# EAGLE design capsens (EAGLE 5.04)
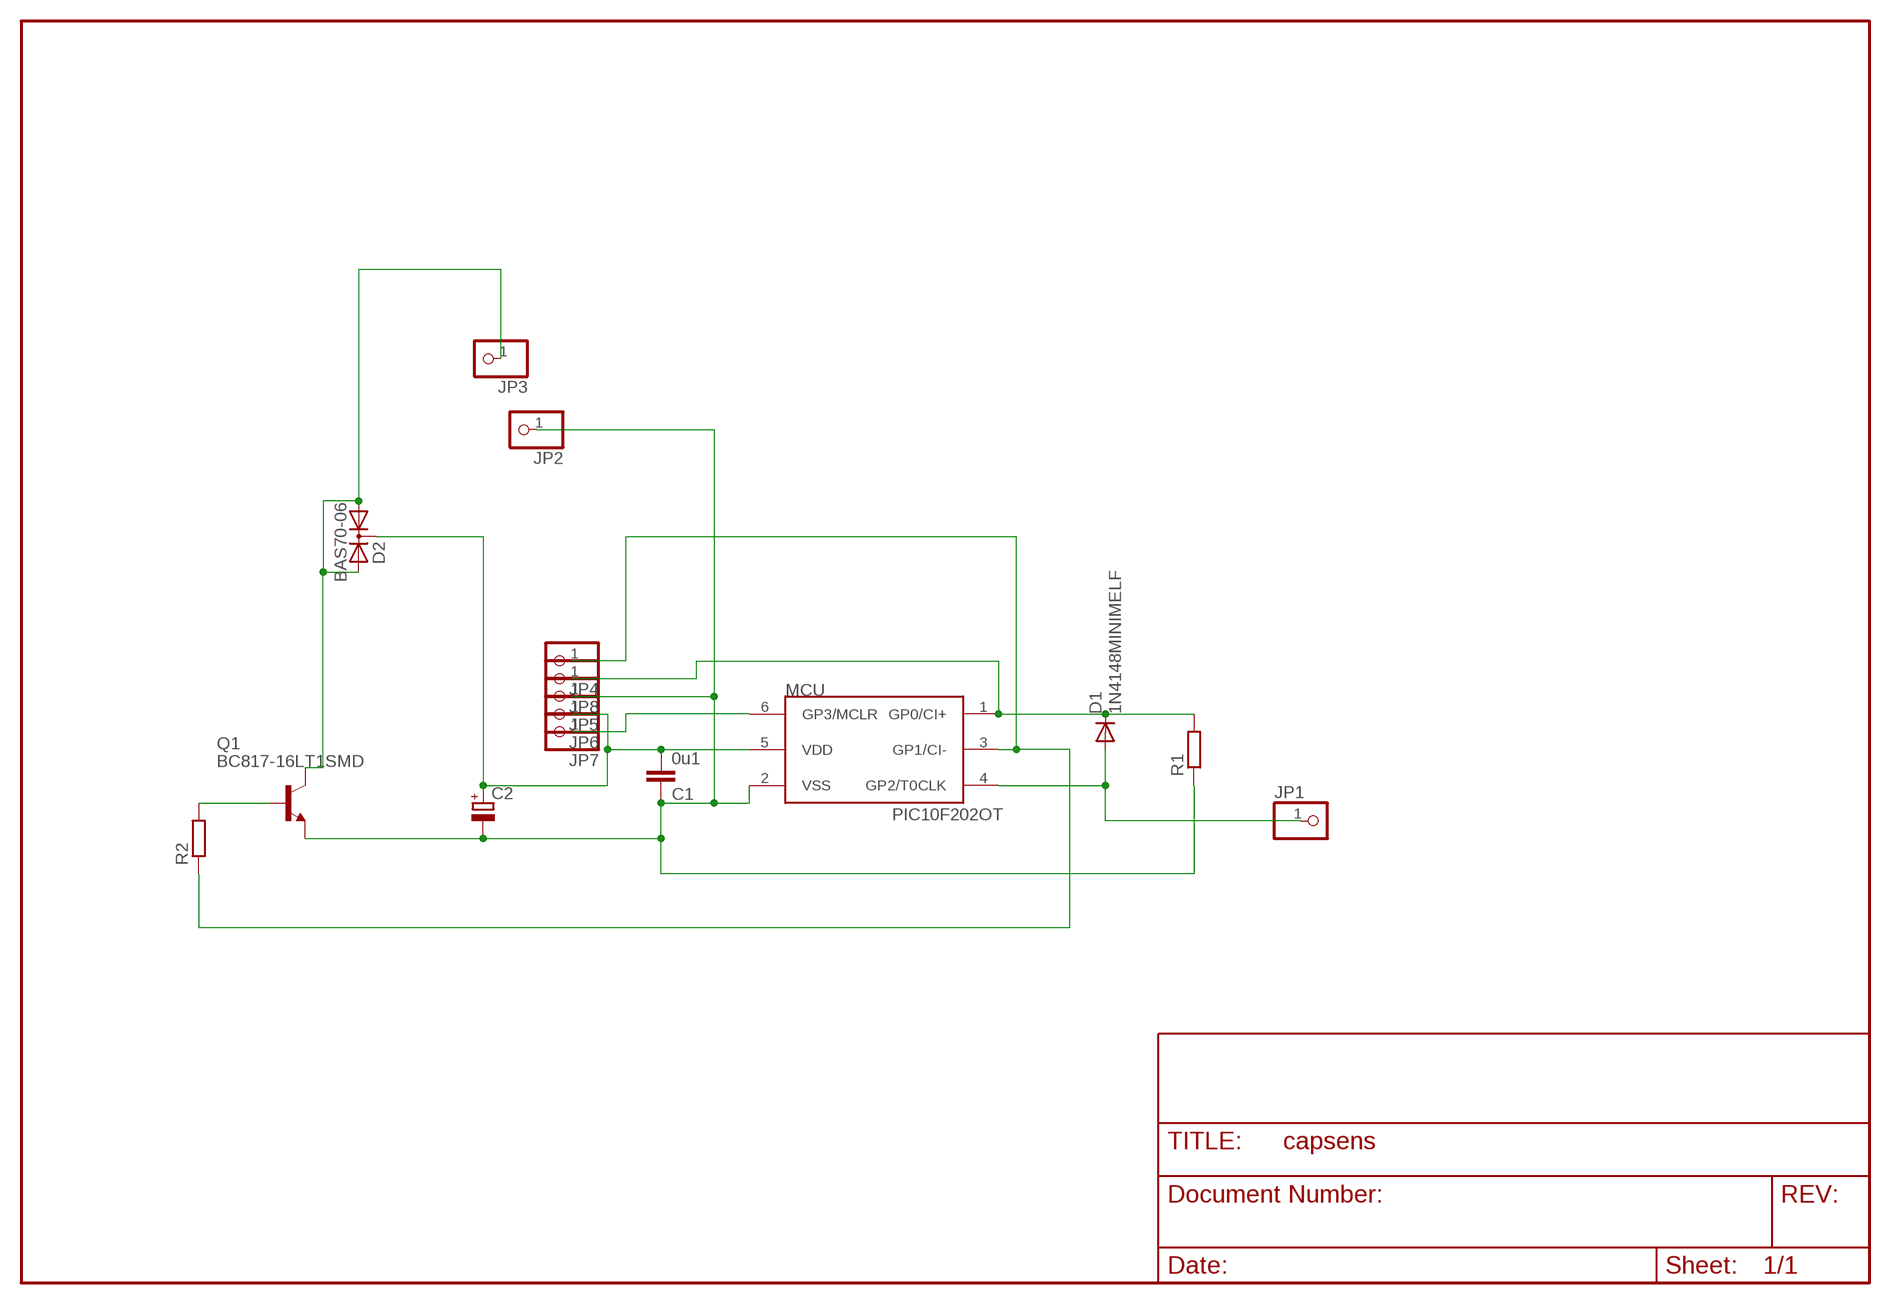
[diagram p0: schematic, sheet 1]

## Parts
C1  0u1  C-EUC1206  [C1206]
C2  CPOL-EUF  [PANASONIC_F]
D1  1N4148MINIMELF  [MINIMELF]
D2  BAS70-06  [SOT23]
JP1  PINHD-1X1  [1X01]
JP2  PINHD-1X1  [1X01]
JP3  PINHD-1X1  [1X01]
JP4  PINHD-1X1  [1X01]
JP5  PINHD-1X1  [1X01]
JP6  PINHD-1X1  [1X01]
JP7  PINHD-1X1  [1X01]
JP8  PINHD-1X1  [1X01]
MCU  PIC10F202OT  [SOT23-6]
Q1  BC817-16LT1SMD  [SOT23-BEC]
R1  R-EU_R1206  [R1206]
R2  R-EU_R1206  [R1206]

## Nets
GP0: D1.C JP8.1 MCU.1(GP0/CI+) R1.2
GP1: JP4.1 MCU.3(GP1/CI-) R2.1
GP2: D1.A JP1.1 MCU.4(GP2/T0CLK)
GP3: JP7.1 MCU.6(GP3/MCLR)
N$1: D2.1(A1) D2.2(A2) JP3.1 Q1.C
N$4: Q1.B R2.2
VDD1: C1.2 C2.+ D2.3(C) JP6.1 MCU.5(VDD)
VSS1: C1.1 C2.- JP2.1 JP5.1 MCU.2(VSS) Q1.E R1.1

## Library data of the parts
C1 = rcl:C-EU: CAPACITOR, European symbol
C2 = rcl-2:CPOL-EU: POLARIZED CAPACITOR, European symbol
D1 = diode-1:1N4148: DIODE
D2 = diode-1:BAS70-06: Silicon Schottky Diodes General-purpose diode for high-speed switching
JP1-JP8 = pinhead(2):PINHD-1X1: PIN HEADER
MCU = microchip-3:PIC10F2*: uPC nW 0,25/0,5k Program Flash memory Comparator
Q1 = transistor-npn:BC817*: NPN Transistor
R1 R2 = rcl-2:R-EU_: RESISTOR, European symbol

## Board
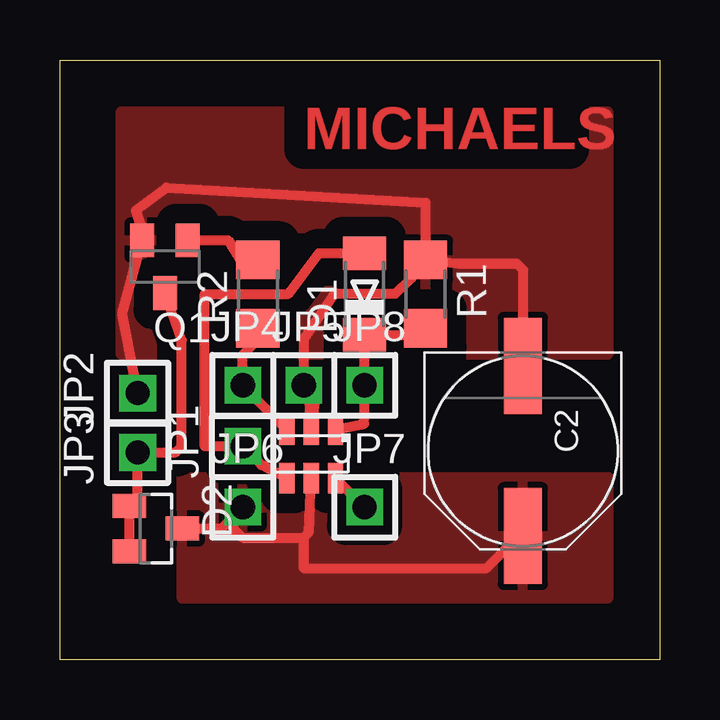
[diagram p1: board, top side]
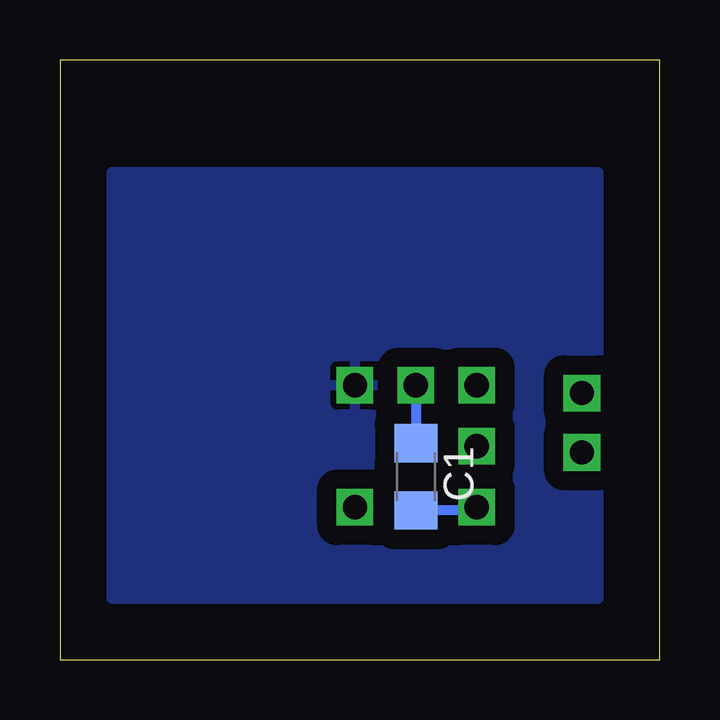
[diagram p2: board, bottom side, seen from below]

Size 25 x 25 mm. Coordinates in mm from the lower left corner, seen from the top.
Outline: 0,0 0,25 25,25 25,0 0,0
Copper layers (1*16): Top 0.035mm / dielectric 1.5mm / Bottom 0.035mm
Design rules "default": minimum track width 10mil, minimum drill 24mil, track to track 8mil, track to pad 8mil, pad to pad 8mil, via to via 8mil, smd to smd 8mil, copper to edge 40mil, drill to drill 8mil, minimum pad ring 10mil, minimum via ring 8mil, stop-mask expansion 4mil, vias tented up to drill 0mil, thermal gap 10mil

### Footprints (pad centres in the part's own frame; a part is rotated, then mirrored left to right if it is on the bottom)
C1206 = smd 1.6 x 1.8: 1 -1.4,0; 2 1.4,0
PANASONIC_F = smd 4 x 1.6: + 3.55,0; - -3.55,0
MINIMELF = smd 1.4 x 1.8: A 1.7,0; C -1.7,0
SOT23 = smd 1 x 1.4: 1 -0.95,-1.1; 2 0.95,-1.1; 3 0,1.1
1X01 = drill 1.016 square: 1 0,0
SOT23-6 = smd 0.635 x 1.27: 1 -1.016,-1.016; 2 0,-1.016; 3 1.016,-1.016; 4 1.016,1.016; 5 0,1.016; 6 -1.016,1.016
SOT23-BEC = smd 1 x 1.4: B -0.95,-1.1; C 0,1.1; E 0.95,-1.1
R1206 = smd 1.6 x 1.803: 1 -1.422,0; 2 1.422,0

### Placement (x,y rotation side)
C1  10.16,7.62 270 bottom
C2  19.3,8.7 270 top
D1  12.7,15.24 90 top
D2  4,5.46 270 top
JP1  7.62,8.89 90 top
JP2  3.24,11.11 90 top
JP3  3.24,8.64 90 top
JP4  7.62,11.43 0 top
JP5  10.16,11.43 0 top
JP6  7.62,6.35 0 top
JP7  12.7,6.35 0 top
JP8  12.7,11.43 0 top
MCU  10.48,8.57 180 top
Q1  4.38,16.38 180 top
R1  15.24,15.24 270 top
R2  8.26,15.24 90 top

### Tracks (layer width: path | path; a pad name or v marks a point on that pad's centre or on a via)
GP0
  Top 0.406: MCU.1 12.68,9.82 12.7,10.16 JP8.1 D1.C 14.33,13.54 R1.2
  pour Bottom (isolate 0.813): 2.54,20.32 22.86,20.32 22.86,2.54 2.54,2.54
GP1
  Top 0.406: MCU.3 9.37,9.68 JP4.1 7.62,12.7 8.74,13.82 R2.1
GP2
  Top 0.406: MCU.4 8.4,8.11 JP1.1 6.03,8.89 6.03,15.24 9.53,15.24 10.79,16.94 D1.A
GP3
  Top 0.406: MCU.6 JP7.1
N$1
  Top 0.406: Q1.C 5.08,13.31 5.08,8.89 4.83,8.64 JP3.1 3.24,6.75 D2.1 D2.2
N$4
  Top 0.406: Q1.B 7,17.48 7.62,16.51 8.74,16.51 R2.2
VDD1
  Top 0.406: D2.3 6.73,5.46 6.99,5.71 | 6.99,5.71 JP6.1 | MCU.5 10.38,5.3 10.16,5.08 | 10.16,5.08 7.62,5.08 6.99,5.71 | C2.+ 19.12,5.15 17.78,3.81 10.16,3.81 10.16,5.08
  Bottom 0.406: C1.2 7.75,6.22 JP6.1
  pour Top (isolate 0.813): 15.24,7.62 22.86,7.62 22.86,2.54 5.08,2.54 5.08,7.62 12.7,7.62
VSS1
  Top 0.406: JP2.1 2.6,14.43 Q1.E 3.49,17.74 3.17,18.73 4.45,19.68 15.24,19.05 R1.1 | C2.- 19.3,16.26 19.05,16.51 16.66,16.51 R1.1 | 10.38,11.21 MCU.2 10.7,11.34 JP5.1 10.16,13.34 11.43,15.24 13.97,15.24 14.61,15.88 R1.1
  Bottom 0.406: JP5.1 C1.1
  pour Top (isolate 0.813): 2.54,12.7 2.54,22.86 22.86,22.86 22.86,12.7

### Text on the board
Top: MICHAELS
